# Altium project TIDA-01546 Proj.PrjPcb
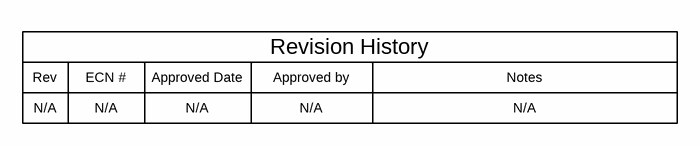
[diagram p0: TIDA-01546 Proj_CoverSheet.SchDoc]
CopyrightYear: 2017; PCB_Layout: Who did the Layout?; PCB_Rev: E2; PRJ_Customer: Public Release; PRJ_Engineer: Enter name of project lead; PRJ_Number: TIDA-01546; PRJ_Title: Change in menu Project|Project Options|Parameters; SCH_Rev: E2; TechSupport: http://www.ti.com/support; TID: TIDA-01546
5 sheets, 178 parts. Net scope: flat (ports and power ports of the same name join across sheets).
Board file: TIDA-01546 Proj_PCB.PcbDoc
Sheets:
  TIDA-01546 Proj_CoverSheet.SchDoc
  TIDA-01546 Proj_SysMonitoring.SchDoc
  TIDA-01546 Proj_BatMonitoring.SchDoc
  TIDA-01546 Proj_SysLoad.SchDoc
  TIDA-01546 Proj_EVM_Hardware.SchDoc

## Sheet TIDA-01546 Proj_CoverSheet.SchDoc
size 431 x 279 mm; Date: Not shown in title block; ApprovedBy: Not shown in title block; CheckedBy: Not shown in title block; Author: Not shown in title block; CompanyName: Not shown in title block; Organization: Not shown in title block; Address1: Not shown in title block; Address2: Not shown in title block; Address3: Not shown in title block; Address4: Not shown in title block; DocumentNumber: 1; Revision: Use project parameter SCH_Rev; SheetNumber: 1; SheetTotal: 3; PageSetup: Record=PageOptions¦CenterHorizontal=True¦CenterVertical=True¦PrintScale=0.64¦XCorrection=1.00¦YCorrection=1.00¦PrintKind=0¦BorderSize=5000000¦LeftOffset=0¦BottomOffset=0¦Orientation=2¦PaperLength=1000¦PaperWidth=1000¦Scale=100¦PaperSource=15¦PrintQuality=600¦MediaType=1¦DitherType=10¦PrintScaleMode=1¦PaperKind=Letter

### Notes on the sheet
- Rev
- N/A
- ECN #
- Approved Date
- Approved by
- Revision History
- Notes

## Sheet TIDA-01546 Proj_SysMonitoring.SchDoc
size 431 x 279 mm; Date: Not shown in title block; ApprovedBy: Not shown in title block; CheckedBy: Not shown in title block; Author: Not shown in title block; CompanyName: Not shown in title block; Engineer: Not shown in title block; Organization: Not shown in title block; Address1: Not shown in title block; Address2: Not shown in title block; Address3: Not shown in title block; Address4: Not shown in title block; DocumentNumber: 1; Revision: Use project parameter SCH_Rev; SheetNumber: 2; SheetTotal: 3; PageSetup: Record=PageOptions¦CenterHorizontal=True¦CenterVertical=True¦PrintScale=1.00¦XCorrection=1.00¦YCorrection=1.00¦PrintKind=0¦BorderSize=5000000¦LeftOffset=0¦BottomOffset=0¦Orientation=2¦PaperLength=1000¦PaperWidth=1000¦Scale=100¦PaperSource=15¦PrintQuality=600¦MediaType=1¦DitherType=10¦PaperKind=Letter¦PrintScaleMode=1
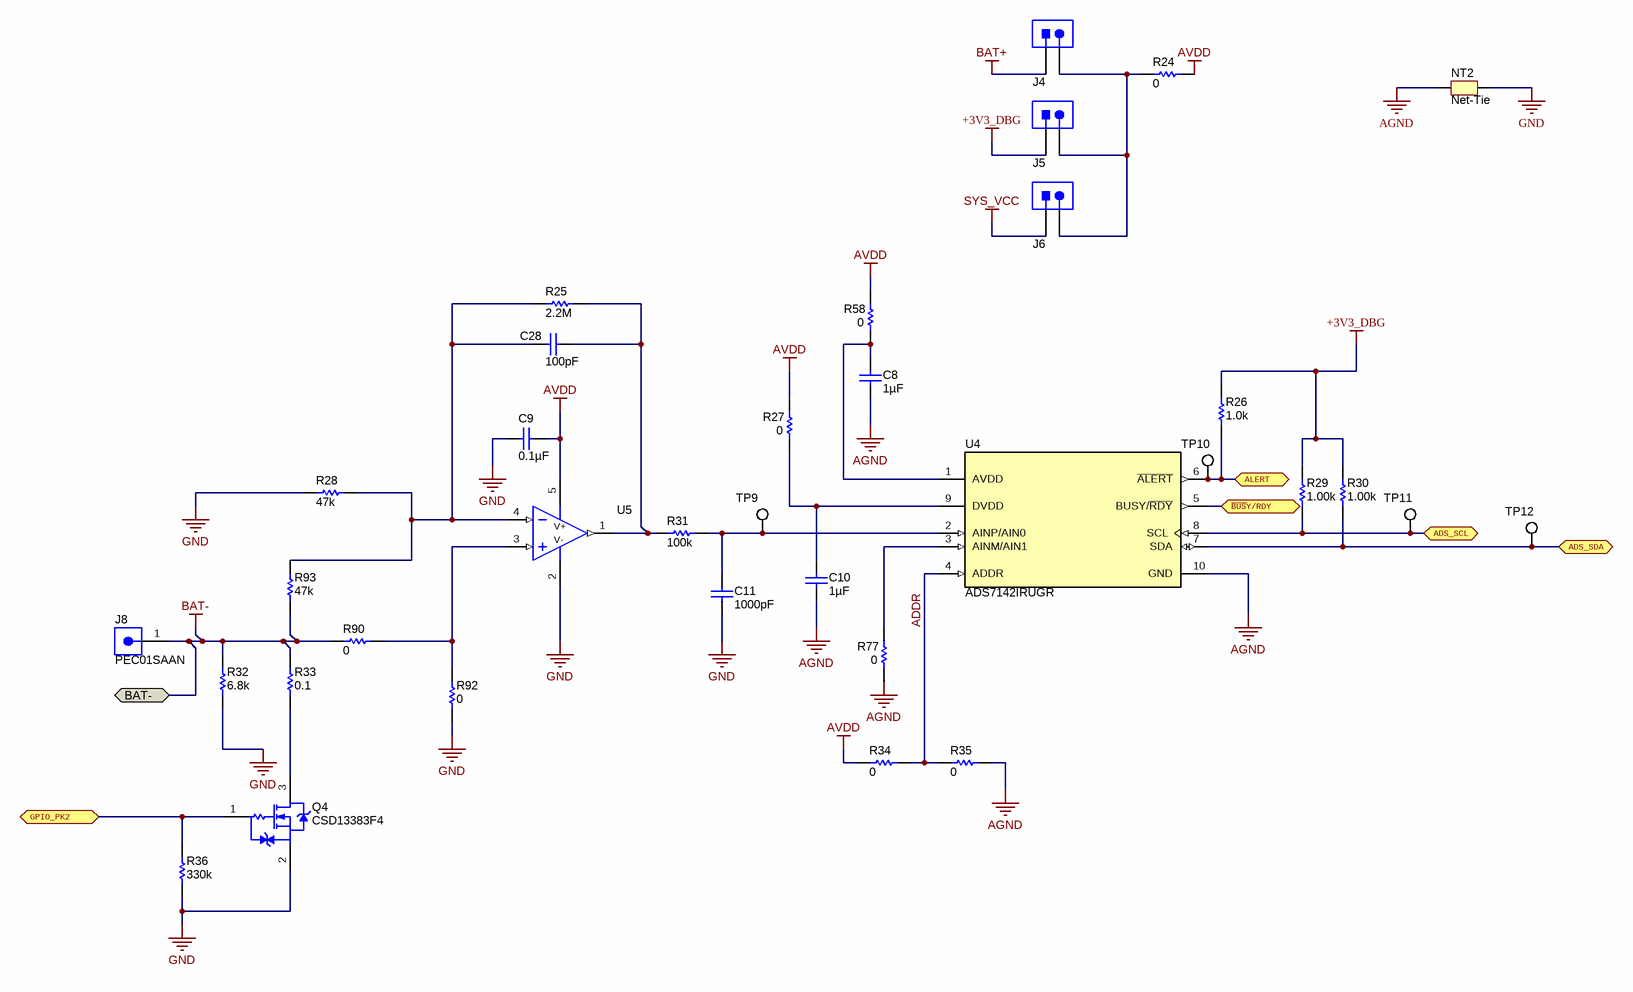
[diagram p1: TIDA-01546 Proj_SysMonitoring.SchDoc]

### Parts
C8  ValueDisplayed: 1µF  [0805_HV]  (hidden comment: GRM21BR71H105KA12L)
C9  ValueDisplayed: 0.1µF  [0402_065]  (hidden comment: 160R07X104KV4T)
C10  ValueDisplayed: 1µF  [0805_HV]  (hidden comment: GRM21BR71H105KA12L)
C11  ValueDisplayed: 1000pF  [1206_190]  (hidden comment: 202R18W102KV4E)
C28  ValueDisplayed: 100pF  [0402]  (hidden comment: 0402YC101KAT2A)
J4  PEC02SAAN  [CONN_PEC02SAAN]  (value not drawn)
J5  PEC02SAAN  [CONN_PEC02SAAN]  (value not drawn)
J6  PEC02SAAN  [CONN_PEC02SAAN]  (value not drawn)
J8  PEC01SAAN  [Sullins_PEC01SAAN]
NT2  Net-Tie  [Net-Tie_50milWide_30milLong]  (net tie, no BOM)
Q4  CSD13383F4  [YJC0003A]
R24  ValueDisplayed: 0  [0402]  (hidden comment: RC0402JR-070RL)
R25  ValueDisplayed: 2.2M  [0603]  (hidden comment: CRCW06032M20JNEA)
R26  value 1.0k  [0603]  (hidden comment: CRCW06031K00JNEA)
R27  ValueDisplayed: 0  [0402]  (hidden comment: RC0402JR-070RL)
R28  ValueDisplayed: 47k  [0603]  (hidden comment: CRCW060347K0JNEA)
R29  ValueDisplayed: 1.00k  [0603]  (hidden comment: CRCW06031K00FKEA)
R30  ValueDisplayed: 1.00k  [0603]  (hidden comment: CRCW06031K00FKEA)
R31  ValueDisplayed: 100k  [0603]  (hidden comment: CRCW0603100KJNEA)
R32  ValueDisplayed: 6.8k  [2010]  (hidden comment: CRCW20106K80JNEF)
R33  ValueDisplayed: 0.1  [2010]  (hidden comment: WSL2010R1000FEA)
R34  ValueDisplayed: 0  [0402]  (hidden comment: RC0402JR-070RL)
R35  ValueDisplayed: 0  [0402]  (hidden comment: RC0402JR-070RL)
R36  ValueDisplayed: 330k  [0805_HV]  (hidden comment: CRCW0805330KJNEA)
R58  ValueDisplayed: 0  [0402]  (hidden comment: RC0402JR-070RL)
R77  ValueDisplayed: 0  [0402]  (hidden comment: RC0402JR-070RL)
R90  ValueDisplayed: 0  [0402]  (hidden comment: RC0402JR-070RL)
R92  ValueDisplayed: 0  [0402]  (hidden comment: RC0402JR-070RL)
R93  ValueDisplayed: 47k  [0402]  (hidden comment: CRCW040247K0JNED)
TP9  5002  [Keystone5002]  (value not drawn)
TP10  5002  [Keystone5002]  (value not drawn)
TP11  5002  [Keystone5002]  (value not drawn)
TP12  5002  [Keystone5002]  (value not drawn)
U4  PartNumber: ADS7142IRUGR  [RUG0010A]  (hidden comment: CMP-0065258-3)
U5  LPV521MG  [DCK0005A_N]  (value not drawn)

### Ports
ADS_SCL, ADS_SDA, ALERT, BAT- (bidir), GPIO_PK2, ~{BUS}Y/RDY

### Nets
+3V3_DBG: J5.1 R26.1 R29.1 R30.1
AGND: C8.1 C10.1 NT2.1 R35.2 R77.1 U4.10(GND)
AVDD: C9.1 R24.2 R27.2 R34.1 R58.2 U5.5(V+)
BAT+: J4.1
BAT-: J8.1 R32.1 R33.1 R90.1 R93.1 ; port BAT-
GND: C9.2 C11.1 NT2.2 Q4.2(S) R28.1 R32.2 R36.2 R92.1 U5.2(V-)
SYS_VCC: J6.1
ADDR: R34.2 R35.1 U4.4(ADDR)
ADS_SCL: R29.2 TP11.1 U4.8(SCL) ; port ADS_SCL
ADS_SDA: R30.2 TP12.1 U4.7(SDA) ; port ADS_SDA
ALERT: R26.2 TP10.1 U4.6(~{ALERT}) ; port ALERT
~{BUS}Y/RDY: U4.5(BUSY/~{RDY}) ; port ~{BUS}Y/RDY
GPIO_PK2: Q4.1(G) R36.1 ; port GPIO_PK2
NetC8_2: C8.2 R58.1 U4.1(AVDD)
NetC10_2: C10.2 R27.1 U4.9(DVDD)
NetC11_2: C11.2 R31.2 TP9.1 U4.2(AINP/AIN0)
NetC28_1: C28.1 R25.2 R31.1 U5.1(OUT)
NetC28_2: C28.2 R25.1 R28.2 R93.2 U5.4(IN-)
NetJ4_2: J4.2 J5.2 J6.2 R24.1
NetQ4_3: Q4.3(D) R33.2
NetR77_2: R77.2 U4.3(AINM/AIN1)
NetR90_2: R90.2 R92.2 U5.3(IN+)

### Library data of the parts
C8 C10 = GRM21BR71H105KA12L: CAP, CERM, 1 µF, 50 V, +/- 10%, X7R, 0805; Manufacturer: MuRata; Polarized: N; CompType: Capacitor; Value: 1uF; U/M: EA; Cap_F: 0.000001; Tolerance_%: 10; Value1: Unknown; VDC_V: 50; Value2: 50V; TaMin_C: -55; TaMax_C: 125; Cap_Case: 0805; AEC Category: Q200
C9 = 160R07X104KV4T: CAP, CERM, 0.1 µF, 16 V,+/- 10%, X5R, 0402; Manufacturer: Johanson Technology; Polarized: N; CompType: Capacitor; Value: 0.1uF; U/M: EA; Cap_F: 0.0000001; Tolerance_%: 10; VDC_V: 16; Value2: 16V; TaMin_C: -55; TaMax_C: 85; Cap_Case: 0402; SizeArea_mm2: 0.5; SizeAreaWB_mm2: 3; SizeX_mm: 1; SizeZ_mm: 0.65; AEC Category: Q200; Green_Lifecycle: Not Set; Green_REACh: Incomplete
C11 = 202R18W102KV4E: CAP, CERM, 1000 pF, 2000 V,+/- 10%, X7R, 1206; Manufacturer: Johanson Technology; Polarized: N; CompType: Capacitor; Value: 1000pF; U/M: EA; Cap_F: 0.000000001; Tolerance_%: 10; VDC_V: 2000; Value2: 2000V; TaMin_C: -55; TaMax_C: 125; Cap_Case: 1206; SizeArea_mm2: 5.12; SizeAreaWB_mm2: 10.92; SizeX_mm: 3.2; SizeY_mm: 1.6; SizeZ_mm: 1.9; AEC Category: Q200
C28 = 0402YC101KAT2A: CAP, CERM, 100 pF, 16 V,+/- 10%, X7R, 0402; Manufacturer: AVX; Polarized: N; CompType: Capacitor; Value: 100pF; U/M: EA; Cap_F: 0.0000000001; Tolerance_%: 10; VDC_V: 16; Value2: 16V; TaMin_C: -55; TaMax_C: 125; SizeArea_mm2: 0.5; SizeAreaWB_mm2: 3; SizeX_mm: 1; SizeZ_mm: 0.6; AEC Category: Q200
J4-J6 = PEC02SAAN: Header, 100mil, 2x1, Tin, TH; Manufacturer: Sullins Connector Solutions; SymbolCreator: a0412235; Pitch_mm: 2.54; Gender: Male; Shrouded: N; Row_Count: 1; Current_A: 3; Voltage_V: 1800; Cert_UL: Y
J8 = PEC01SAAN: Header, 1x1, Tin, TH; Manufacturer: Sullins Connector Solutions; SymbolCreator: a0412235; Pitch_mm: 2.54; Gender: Male; Shrouded: N; Row_Count: 1; Current_A: 3; Voltage_V: 1800; Cert_UL: Y; Green_Lifecycle: Not Set; Green_REACh: Incomplete
NT2 = Net-Tie: Single point connection between nets.; SymbolCreator: codlsc
Q4 = CSD13383F4: MOSFET, N-CH, 12 V, 2.9 A, YJC0003A (PICOSTAR-3); Manufacturer: Texas Instruments; Alternate Manufacturer: None; SymbolCreator: a0411947; U/M: EA; ChType: N; Value: 12V; VdsMax_V: 12; Value1: 0.044 ohm; Rdson45_ohm: 0.044; Value2: 2 nC; QgTyp_nC: 2; Vgs_V: 10; IdsMax_A: 2.9; SizeAreaWB_mm2: 3.327225; SizeArea_mm2: 0.657225; SizeX_mm: 1.035; SizeY_mm: 0.635; SizeZ_mm: 0.35; AEC Category: Q101
R24 R27 R34 R35 R58 R77 R90 R92 = RC0402JR-070RL: RES, 0, 5%, 0.063 W, 0402; Manufacturer: Yageo America; CompType: Resistor; Value: 0; Value_Code: 0000; Tolerance_%: 5; Power_W: 0.063; Value2: 0.063W; VDC_V: 50; TempCo: 200 ppm/C; EIA_Code: E24; U/M: EA; AEC Category: Q200
R25 = CRCW06032M20JNEA: RES, 2.2 M, 5%, 0.1 W, 0603; Manufacturer: Vishay-Dale; CompType: Resistor; Value: 2.2Meg; Res_ohm: 2200000; Value_Code: 2M20; Tolerance_%: 5; Power_W: 0.1; Value2: 0.1W; VDC_V: 75; TempCo: 200 ppm/C; SizeArea_mm2: 1.28; SizeX_mm: 1.6; SizeY_mm: 0.8; SizeZ_mm: 1; EIA_Code: E24; U/M: EA; AEC Category: Q200
R26 = CRCW06031K00JNEA: RES, 1.0k ohm, 5%, 0.1W, 0603; Manufacturer: Vishay-Dale; CompType: Resistor; Res_ohm: 1000; Value_Code: 1k00; Tolerance_%: 5; Power_W: 0.1; VDC_V: 75; TempCo: 200 ppm/C; EIA_Code: E24; U/M: EA
R28 = CRCW060347K0JNEA: RES, 47 k, 5%, 0.1 W, 0603; Manufacturer: Vishay-Dale; CompType: Resistor; Value: 47k; Res_ohm: 47000; Value_Code: 47k0; Tolerance_%: 5; Power_W: 0.1; Value2: 0.1W; VDC_V: 75; TempCo: 200 ppm/C; SizeArea_mm2: 1.28; SizeX_mm: 1.6; SizeY_mm: 0.8; SizeZ_mm: 1; EIA_Code: E24; U/M: EA; AEC Category: Q200; Green_Lifecycle: Active; Green_REACh: Passed
R29 R30 = CRCW06031K00FKEA: RES, 1.00 k, 1%, 0.1 W, 0603; Manufacturer: Vishay-Dale; CompType: Resistor; Value: 1.00k; Res_ohm: 1000; Value_Code: 1k00; Tolerance_%: 1; Power_W: 0.1; Value2: 0.1W; VDC_V: 75; TempCo: 100 ppm/C; EIA_Code: E96; U/M: EA; AEC Category: Q200; SizeArea_mm2: 1.28; SizeX_mm: 1.6; SizeY_mm: 0.8; Green_Lifecycle: Active; Green_REACh: Passed
R31 = CRCW0603100KJNEA: RES, 100 k, 5%, 0.1 W, 0603; Manufacturer: Vishay-Dale; CompType: Resistor; Value: 100k; Res_ohm: 100000; Tolerance_%: 5; Power_W: 0.1; Value2: 0.1W; VDC_V: 75; TempCo: 200 ppm/C; SizeArea_mm2: 1.28; SizeX_mm: 1.6; SizeY_mm: 0.8; SizeZ_mm: 1; EIA_Code: E24; U/M: EA; AEC Category: Q200; Green_Lifecycle: Active; Green_REACh: Passed
R32 = CRCW20106K80JNEF: RES, 6.8 k, 5%, 0.75 W, AEC-Q200 Grade 0, 2010; Manufacturer: Vishay-Dale; CompType: Resistor; Value: 6.8k; Res_ohm: 6800; Value_Code: 6k80; Tolerance_%: 5; Power_W: 0.75; Value2: 0.75W; VDC_V: 400; TempCo: 200 ppm/C; SizeArea_mm2: 12.5; SizeY_mm: 2.5; SizeZ_mm: 1.66; EIA_Code: E24; U/M: EA; AEC Category: Q200; AEC Qualified: Y; AEC Grade: 0
R33 = WSL2010R1000FEA: RES, 0.1, 1%, 0.5 W, 2010; Manufacturer: Vishay-Dale; CompType: Resistor; Value: 0.1; Value_Code: R100; Tolerance_%: 1; Power_W: 0.5; Value2: 0.5W; TempCo: 75 ppm/C; SizeArea_mm2: 12.5; SizeX_mm: 5; SizeY_mm: 2.5; SizeZ_mm: 1.66; EIA_Code: E96; U/M: EA; AEC Category: Q200
R36 = CRCW0805330KJNEA: RES, 330 k, 5%, 0.125 W, 0805; Manufacturer: Vishay-Dale; CompType: Resistor; Value: 330k; Res_ohm: 330000; Tolerance_%: 5; Power_W: 0.125; Value2: 0.125W; VDC_V: 150; TempCo: 200 ppm/C; SizeArea_mm2: 2.5; SizeX_mm: 2; SizeY_mm: 1.25; SizeZ_mm: 1.45; EIA_Code: E24; U/M: EA; AEC Category: Q200
R93 = CRCW040247K0JNED: RES, 47 k, 5%, 0.063 W, 0402; Manufacturer: Vishay-Dale; CompType: Resistor; Value: 47k; Res_ohm: 47000; Value_Code: 47k0; Tolerance_%: 5; Power_W: 0.063; Value2: 0.063W; VDC_V: 50; TempCo: 200 ppm/C; SizeArea_mm2: 0.5; SizeX_mm: 1; SizeZ_mm: 0.6; EIA_Code: E24; U/M: EA; AEC Category: Q200; Green_Lifecycle: Active; Green_REACh: Passed
TP9-TP12 = 5002: Test Point, Miniature, White, TH; Manufacturer: Keystone; CompType: Test Point Loop; U/M: EA
U4 = CMP-0065258-3: Nanopower, Ultra-Small Size, Sensor Monitor with I2C Interface and Alert Output, RUG0010A (X2QFN-10); Alternate PartNumber: ADS7142IRUGT; Manufacturer: Texas Instruments; SizeArea_mm2: 3.0; SizeAreaWB_mm2: 7.5; SizeX_mm: 1.5; SizeY_mm: 2.0; SizeZ_mm: 0.4; CompType: IC; U/M: EA
U5 = LPV521MG: Nanopower 400nA, 1.8V, R-R I/O CMOS Op Amp, DCK0005A; Manufacturer: Texas Instruments; CompType: OpAmp IC

## Sheet TIDA-01546 Proj_BatMonitoring.SchDoc
size 431 x 279 mm; Date: Not shown in title block; ApprovedBy: Not shown in title block; CheckedBy: Not shown in title block; Author: Not shown in title block; CompanyName: Not shown in title block; Engineer: Not shown in title block; Organization: Not shown in title block; Address1: Not shown in title block; Address2: Not shown in title block; Address3: Not shown in title block; Address4: Not shown in title block; DocumentNumber: 1; Revision: Use project parameter SCH_Rev; SheetNumber: 2; SheetTotal: 3; PageSetup: Record=PageOptions¦CenterHorizontal=True¦CenterVertical=True¦PrintScale=1.00¦XCorrection=1.00¦YCorrection=1.00¦PrintKind=0¦BorderSize=5000000¦LeftOffset=0¦BottomOffset=0¦Orientation=2¦PaperLength=1000¦PaperWidth=1000¦Scale=100¦PaperSource=15¦PrintQuality=600¦MediaType=1¦DitherType=10¦PaperKind=Letter¦PrintScaleMode=1
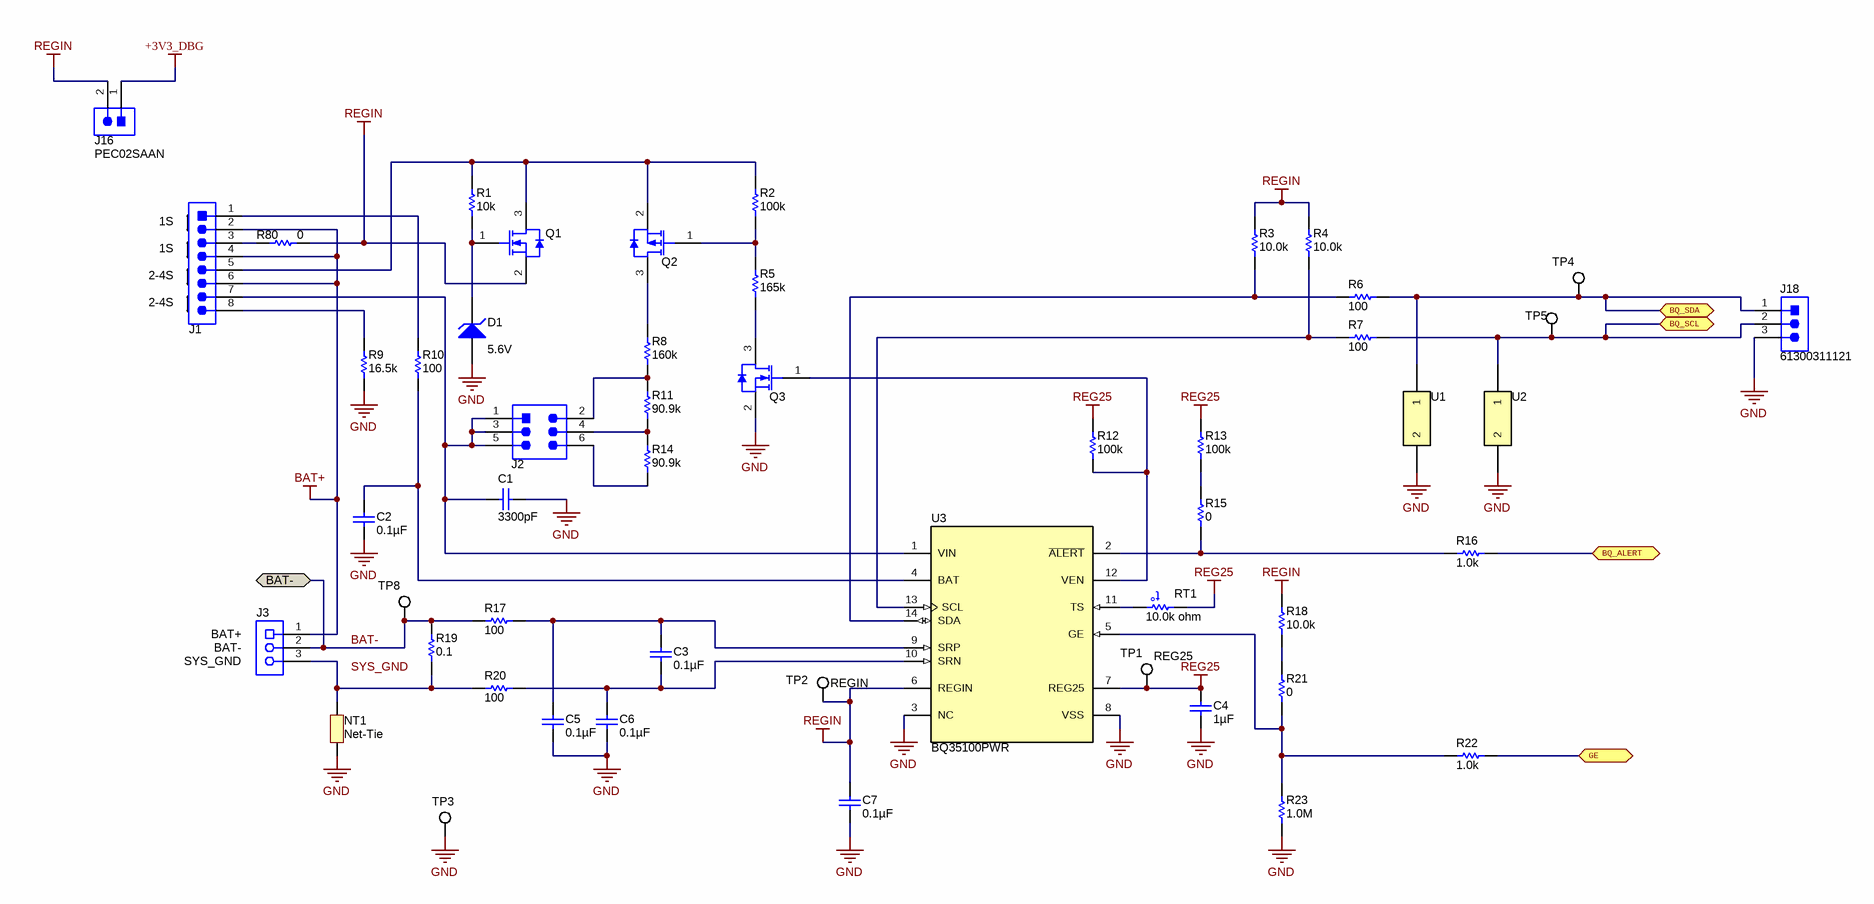
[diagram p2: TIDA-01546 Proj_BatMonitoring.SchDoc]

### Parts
C1  ValueDisplayed: 3300pF  [0603]  (hidden comment: GRM188R71H332KA01D)
C2  ValueDisplayed: 0.1µF  [0603]  (hidden comment: GRM188R71H104KA93D)
C3  ValueDisplayed: 0.1µF  [0603]  (hidden comment: GRM188R71H104KA93D)
C4  ValueDisplayed: 1µF  [0805_HV]  (hidden comment: GRM21BR71H105KA12L)
C5  ValueDisplayed: 0.1µF  [0603]  (hidden comment: GRM188R71H104KA93D)
C6  ValueDisplayed: 0.1µF  [0603]  (hidden comment: GRM188R71H104KA93D)
C7  ValueDisplayed: 0.1µF  [0603]  (hidden comment: GRM188R71H104KA93D)
D1  value 5.6V  [SOD-523]  (hidden comment: BZT52C5V6T-7)
J1  PEC08SAAN  [SULLINS_PEC08SAAN]  (value not drawn)
J2  PEC03DAAN  [SULLINS_PEC03DAAN]  (value not drawn)
J3  39357-0003  [Molex_39357-0003]  (value not drawn)
J16  PEC02SAAN  [CONN_PEC02SAAN]
J18  61300311121  [WURTH_61300311121]
NT1  Net-Tie  [Net-Tie_10mil]  (net tie, no BOM)
Q1  2N7002-7-F  [SOT-23]  (value not drawn)
Q2  BSS84W-7-F  [SOT-323]  (value not drawn)
Q3  BSS138W-7-F  [SOT-323]  (value not drawn)
R1  value 10k  [0603]  (hidden comment: CRCW060310K0JNEA)
R2  ValueDisplayed: 100k  [0603]  (hidden comment: CRCW0603100KFKEA)
R3  ValueDisplayed: 10.0k  [0603]  (hidden comment: CRCW060310K0FKEA)
R4  ValueDisplayed: 10.0k  [0603]  (hidden comment: CRCW060310K0FKEA)
R5  ValueDisplayed: 165k  [0603]  (hidden comment: CRCW0603165KFKEA)
R6  ValueDisplayed: 100  [0603]  (hidden comment: CRCW0603100RFKEA)
R7  ValueDisplayed: 100  [0603]  (hidden comment: CRCW0603100RFKEA)
R8  ValueDisplayed: 160k  [0603]  (hidden comment: RG1608P-164-B-T5)
R9  ValueDisplayed: 16.5k  [0603]  (hidden comment: RG1608P-1652-B-T5)
R10  ValueDisplayed: 100  [0603]  (hidden comment: CRCW0603100RFKEA)
R11  ValueDisplayed: 90.9k  [0603]  (hidden comment: RG1608P-9092-B-T5)
R12  ValueDisplayed: 100k  [0603]  (hidden comment: CRCW0603100KFKEA)
R13  ValueDisplayed: 100k  [0603]  (hidden comment: CRCW0603100KFKEA)
R14  ValueDisplayed: 90.9k  [0603]  (hidden comment: RG1608P-9092-B-T5)
R15  ValueDisplayed: 0  [0402]  (hidden comment: RC0402JR-070RL)
R16  value 1.0k  [0603]  (hidden comment: CRCW06031K00JNEA)
R17  ValueDisplayed: 100  [0603]  (hidden comment: CRCW0603100RFKEA)
R18  ValueDisplayed: 10.0k  [0603]  (hidden comment: CRCW060310K0FKEA)
R19  ValueDisplayed: 0.1  [2010]  (hidden comment: WSL2010R1000FEA)
R20  ValueDisplayed: 100  [0603]  (hidden comment: CRCW0603100RFKEA)
R21  ValueDisplayed: 0  [0402]  (hidden comment: RC0402JR-070RL)
R22  value 1.0k  [0603]  (hidden comment: CRCW06031K00JNEA)
R23  ValueDisplayed: 1.0M  [0603]  (hidden comment: CRCW06031M00JNEA)
R80  ValueDisplayed: 0  [0402]  (hidden comment: RC0402JR-070RL)
RT1  value 10.0k ohm  [Thermistor_103AT-2]  (hidden comment: 103AT-2)
TP1  5002  [Keystone5002]  (value not drawn)
TP2  5002  [Keystone5002]  (value not drawn)
TP3  5002  [Keystone5002]  (value not drawn)
TP4  5002  [Keystone5002]  (value not drawn)
TP5  5002  [Keystone5002]  (value not drawn)
TP8  5002  [Keystone5002]  (value not drawn)
U1  TPD1E10B06DPYR  [DPY0002A]  (value not drawn)
U2  TPD1E10B06DPYR  [DPY0002A]  (value not drawn)
U3  BQ35100PWR  [PW0014A_N]

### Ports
BAT- (bidir), BQ_ALERT, BQ_SCL, BQ_SDA, GE

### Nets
+3V3_DBG: J16.1
BAT+: J1.2 J1.4 J1.6 J3.1
BAT-: J3.2 R17.1 R19.1 TP8.1 ; port BAT-
GND: C1.2 C2.1 C4.1 C5.1 C6.1 C7.1 D1.2(A) J18.3 NT1.2 Q3.2(S) R9.2 R23.2 TP3.1 U1.2 U2.2 U3.3(NC) U3.8(VSS)
REG25: C4.2 R12.1 R13.1 RT1.1 TP1.1 U3.7(REG25)
REGIN: C7.2 J16.2 Q1.2(S) R3.1 R4.1 R18.1 R80.1 TP2.1 U3.6(REGIN)
BQ_ALERT: R16.2 ; port BQ_ALERT
BQ_SCL: J18.2 R7.2 TP5.1 U2.1 ; port BQ_SCL
BQ_SDA: J18.1 R6.2 TP4.1 U1.1 ; port BQ_SDA
GE: R22.2 ; port GE
NetC1_1: C1.1 J1.7 J2.1 J2.3 J2.5 U3.1(VIN)
NetC2_2: C2.2 R10.2 U3.4(BAT)
NetC3_1: C3.1 C6.2 R20.2 U3.10(SRN)
NetC3_2: C3.2 C5.2 R17.2 U3.9(SRP)
NetD1_1: D1.1(K) Q1.1(G) R1.2
NetJ1_1: J1.1 R10.1
NetJ1_3: J1.3 R80.2
NetJ1_5: J1.5 Q1.3(D) Q2.2(S) R1.1 R2.1
NetJ1_8: J1.8 R9.1
NetJ2_2: J2.2 R8.2 R11.1
NetJ2_4: J2.4 R11.2 R14.2
NetJ2_6: J2.6 R14.1
NetJ3_3: J3.3 NT1.1 R19.2 R20.1
NetQ2_1: Q2.1(G) R2.2 R5.1
NetQ2_3: Q2.3(D) R8.1
NetQ3_1: Q3.1(G) R12.2 U3.12(VEN)
NetQ3_3: Q3.3(D) R5.2
NetR3_2: R3.2 R6.1 U3.14(SDA)
NetR4_2: R4.2 R7.1 U3.13(SCL)
NetR13_2: R13.2 R15.1
NetR15_2: R15.2 R16.1 U3.2(~{ALERT})
NetR18_2: R18.2 R21.1
NetR21_2: R21.2 R22.1 R23.1 U3.5(GE)
NetRT1_2: RT1.2 U3.11(TS)

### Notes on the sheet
- (near J1) 1S
- (near J1) 2-4S
- (near J3) BAT+
- (near J3) BAT-
- (near J3) SYS_GND
- (near TP2) REGIN
- (near TP1) REG25
- Labels drawn without touching a wire or pin: SYS_GND

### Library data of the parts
C1 = GRM188R71H332KA01D: CAP, CERM, 3300 pF, 50 V, +/- 10%, X7R, 0603; Manufacturer: MuRata; Polarized: N; CompType: Capacitor; Value: 3300pF; U/M: EA; Cap_F: 0.0000000033; Tolerance_%: 10; Value1: Unknown; VDC_V: 50; Value2: 50V; TaMin_C: -55; TaMax_C: 125; AEC Category: Q200
C2 C3 C5-C7 = GRM188R71H104KA93D: CAP, CERM, 0.1 µF, 50 V, +/- 10%, X7R, 0603; Manufacturer: MuRata; Polarized: N; CompType: Capacitor; Value: 0.1uF; U/M: EA; Cap_F: 0.0000001; Tolerance_%: 10; Value1: Unknown; VDC_V: 50; Value2: 50V; TaMin_C: -55; TaMax_C: 125; AEC Category: Q200
C4 = GRM21BR71H105KA12L: as C8 on sheet TIDA-01546 Proj_SysMonitoring
D1 = BZT52C5V6T-7: Diode, Zener, 5.6 V, 300 mW, SOD-523; Manufacturer: Diodes Inc.; SymbolCreator: a0412235; U/M: EA; Power_W: 0.3; Vz_V: 5.6; Value1: 0.3W; RJA_CperW: 417; AEC Category: Q101
J1 = PEC08SAAN: Header, 100mil, 8x1, Tin, TH; Manufacturer: Sullins Connector Solutions; SymbolCreator: a0411947; Pitch_mm: 2.54; Gender: Male; Shrouded: N; Row_Count: 1; Current_A: 3; Voltage_V: 1800; Cert_UL: Y
J2 = PEC03DAAN: Header, 100mil, 3x2, Tin, TH; Manufacturer: Sullins Connector Solutions; SymbolCreator: a0412235; Pitch_mm: 2.54; Gender: Male; Shrouded: N; Row_Count: 2; Current_A: 3; Voltage_V: 1800; Cert_UL: Y
J3 = 39357-0003: Terminal Block, 3.5 mm, 3x1, Tin, TH; Manufacturer: Molex; SymbolCreator: a0412235
J16 = PEC02SAAN: Header, 100mil, 2x1, Tin, TH; Manufacturer: Sullins Connector Solutions; SymbolCreator: a0412235; Pitch_mm: 2.54; Gender: Male; Shrouded: N; Row_Count: 1; Current_A: 3; Voltage_V: 1800; Cert_UL: Y; Green_Lifecycle: Not Set; Green_REACh: Incomplete
J18 = 61300311121: Header, 2.54 mm, 3x1, Gold, TH; Manufacturer: Wurth Elektronik; SymbolCreator: a0799628; Green_Lifecycle: Active; Green_REACh: Passed
NT1 = Net-Tie: as NT2 on sheet TIDA-01546 Proj_SysMonitoring
Q1 = 2N7002-7-F: MOSFET, N-CH, 60 V, 0.17 A, SOT-23; Manufacturer: Diodes Inc.; Alternate Manufacturer: None; U/M: EA; ChType: N; Value: 60V; VdsMax_V: 60; Value1: 7.5 ohm; Rdson45_ohm: 7.5; Value2: 223 nC; QgTyp_nC: 223; Vgs_V: 20; IdsMax_A: 0.17; AEC Category: Q101
Q2 = BSS84W-7-F: MOSFET, P-CH, -50 V, -0.13 A, SOT-323; Manufacturer: Diodes Inc.; Alternate Manufacturer: None; U/M: EA; ChType: P; Value: -50V; Value1: 10 ohm; Rdson45_ohm: 10; Value2: ? nC; Vgs_V: -20; AEC Category: Q101
Q3 = BSS138W-7-F: MOSFET, N-CH, 50 V, 0.2 A, SOT-323; Manufacturer: Diodes Inc.; Alternate Manufacturer: None; U/M: EA; ChType: N; Value: 50V; VdsMax_V: 50; Value1: 3.5 ohm; Rdson45_ohm: 3.5; Value2: ? nC; Vgs_V: 1.5; IdsMax_A: 0.2; AEC Category: Q101
R1 = CRCW060310K0JNEA: RES, 10k ohm, 5%, 0.1W, 0603; Manufacturer: Vishay-Dale; CompType: Resistor; Res_ohm: 10000; Value_Code: 10k0; Tolerance_%: 5; Power_W: 0.1; VDC_V: 75; TempCo: 200 ppm/C; EIA_Code: E24; U/M: EA
R2 R12 R13 = CRCW0603100KFKEA: RES, 100 k, 1%, 0.1 W, 0603; Manufacturer: Vishay-Dale; CompType: Resistor; Value: 100k; Res_ohm: 100000; Tolerance_%: 1; Power_W: 0.1; Value2: 0.1W; VDC_V: 75; TempCo: 100 ppm/C; EIA_Code: E96; U/M: EA; AEC Category: Q200
R3 R4 R18 = CRCW060310K0FKEA: RES, 10.0 k, 1%, 0.1 W, 0603; Manufacturer: Vishay-Dale; CompType: Resistor; Value: 10.0k; Res_ohm: 10000; Value_Code: 10k0; Tolerance_%: 1; Power_W: 0.1; Value2: 0.1W; VDC_V: 75; TempCo: 100 ppm/C; EIA_Code: E96; U/M: EA; AEC Category: Q200
R5 = CRCW0603165KFKEA: RES, 165 k, 1%, 0.1 W, 0603; Manufacturer: Vishay-Dale; CompType: Resistor; Value: 165k; Res_ohm: 165000; Tolerance_%: 1; Power_W: 0.1; Value2: 0.1W; VDC_V: 75; TempCo: 100 ppm/C; EIA_Code: E96; U/M: EA; AEC Category: Q200
R6 R7 R10 R17 R20 = CRCW0603100RFKEA: RES, 100, 1%, 0.1 W, 0603; Manufacturer: Vishay-Dale; CompType: Resistor; Value: 100; Value_Code: 100R; Tolerance_%: 1; Power_W: 0.1; Value2: 0.1W; VDC_V: 75; TempCo: 100 ppm/C; EIA_Code: E96; U/M: EA; AEC Category: Q200
R8 = RG1608P-164-B-T5: RES, 160 k, 0.1%, 0.1 W, 0603; Manufacturer: Susumu Co Ltd; CompType: Resistor; Value: 160k; Res_ohm: 160000; Tolerance_%: 0.1; Value2: 0.1W; VDC_V: 75; TempCo: 25 ppm/C; EIA_Code: E192; U/M: EA; AEC Category: Q200
R9 = RG1608P-1652-B-T5: RES, 16.5 k, 0.1%, 0.1 W, 0603; Manufacturer: Susumu Co Ltd; CompType: Resistor; Value: 16.5k; Res_ohm: 16500; Value_Code: 16k5; Tolerance_%: 0.1; Value2: 0.1W; VDC_V: 75; TempCo: 25 ppm/C; EIA_Code: E192; U/M: EA; AEC Category: Q200
R11 R14 = RG1608P-9092-B-T5: RES, 90.9 k, 0.1%, 0.1 W, 0603; Manufacturer: Susumu Co Ltd; CompType: Resistor; Value: 90.9k; Res_ohm: 90900; Value_Code: 90k9; Tolerance_%: 0.1; Value2: 0.1W; VDC_V: 75; TempCo: 25 ppm/C; EIA_Code: E192; U/M: EA; AEC Category: Q200
R15 R21 R80 = RC0402JR-070RL: as R24 on sheet TIDA-01546 Proj_SysMonitoring
R16 R22 = CRCW06031K00JNEA: as R26 on sheet TIDA-01546 Proj_SysMonitoring
R19 = WSL2010R1000FEA: as R33 on sheet TIDA-01546 Proj_SysMonitoring
R23 = CRCW06031M00JNEA: RES, 1.0 M, 5%, 0.1 W, 0603; Manufacturer: Vishay-Dale; CompType: Resistor; Value: 1.0Meg; Res_ohm: 1000000; Value_Code: 1M00; Tolerance_%: 5; Power_W: 0.1; Value2: 0.1W; VDC_V: 75; TempCo: 200 ppm/C; EIA_Code: E24; U/M: EA; AEC Category: Q200
RT1 = 103AT-2: Thermistor NTC, 10.0k ohm, 1%, Disc, 5x8.4 mm; Manufacturer: SEMITEC Corporation; Tolerance_%: 1; Power_W: 0.01; TaMin_C: -50; TaMax_C: 110; U/M: EA
TP1-TP5 TP8 = 5002: as TP9 on sheet TIDA-01546 Proj_SysMonitoring
U1 U2 = TPD1E10B06DPYR: ESD in 0402 Package with 10 pF Capacitance and 6 V Breakdown, 1 Channel, -40 to +125 degC, 2-pin X2SON (DPY), Green (RoHS & no Sb/Br); Manufacturer: Texas Instruments; Alternate PartNumber: Equivalent; Breakdown Voltage(Min)(V): 6; Eco-Plan: TBD; IEC 61000-4-2 Air-Gap(+/- kV): 30; IO Capacitance(Typ)(pF): 10; SubFamily: ESD Solution
U3 = BQ35100PWR: Single Lithium Primary State-of-Health and End-of-Service Monitor, PW0014A; Manufacturer: Texas Instruments; SymbolCreator: Altium; CompType: IC; U/M: EA

## Sheet TIDA-01546 Proj_SysLoad.SchDoc
size 431 x 279 mm; Date: Not shown in title block; ApprovedBy: Not shown in title block; CheckedBy: Not shown in title block; Author: Not shown in title block; CompanyName: Not shown in title block; Engineer: Not shown in title block; Organization: Not shown in title block; Address1: Not shown in title block; Address2: Not shown in title block; Address3: Not shown in title block; Address4: Not shown in title block; DocumentNumber: 1; Revision: Use project parameter SCH_Rev; SheetNumber: 2; SheetTotal: 3; PageSetup: Record=PageOptions¦CenterHorizontal=True¦CenterVertical=True¦PrintScale=1.00¦XCorrection=1.00¦YCorrection=1.00¦PrintKind=0¦BorderSize=5000000¦LeftOffset=0¦BottomOffset=0¦Orientation=2¦PaperLength=1000¦PaperWidth=1000¦Scale=100¦PaperSource=15¦PrintQuality=-3¦MediaType=1¦DitherType=10¦PrintScaleMode=1¦PaperKind=Letter¦PaperIndex=1
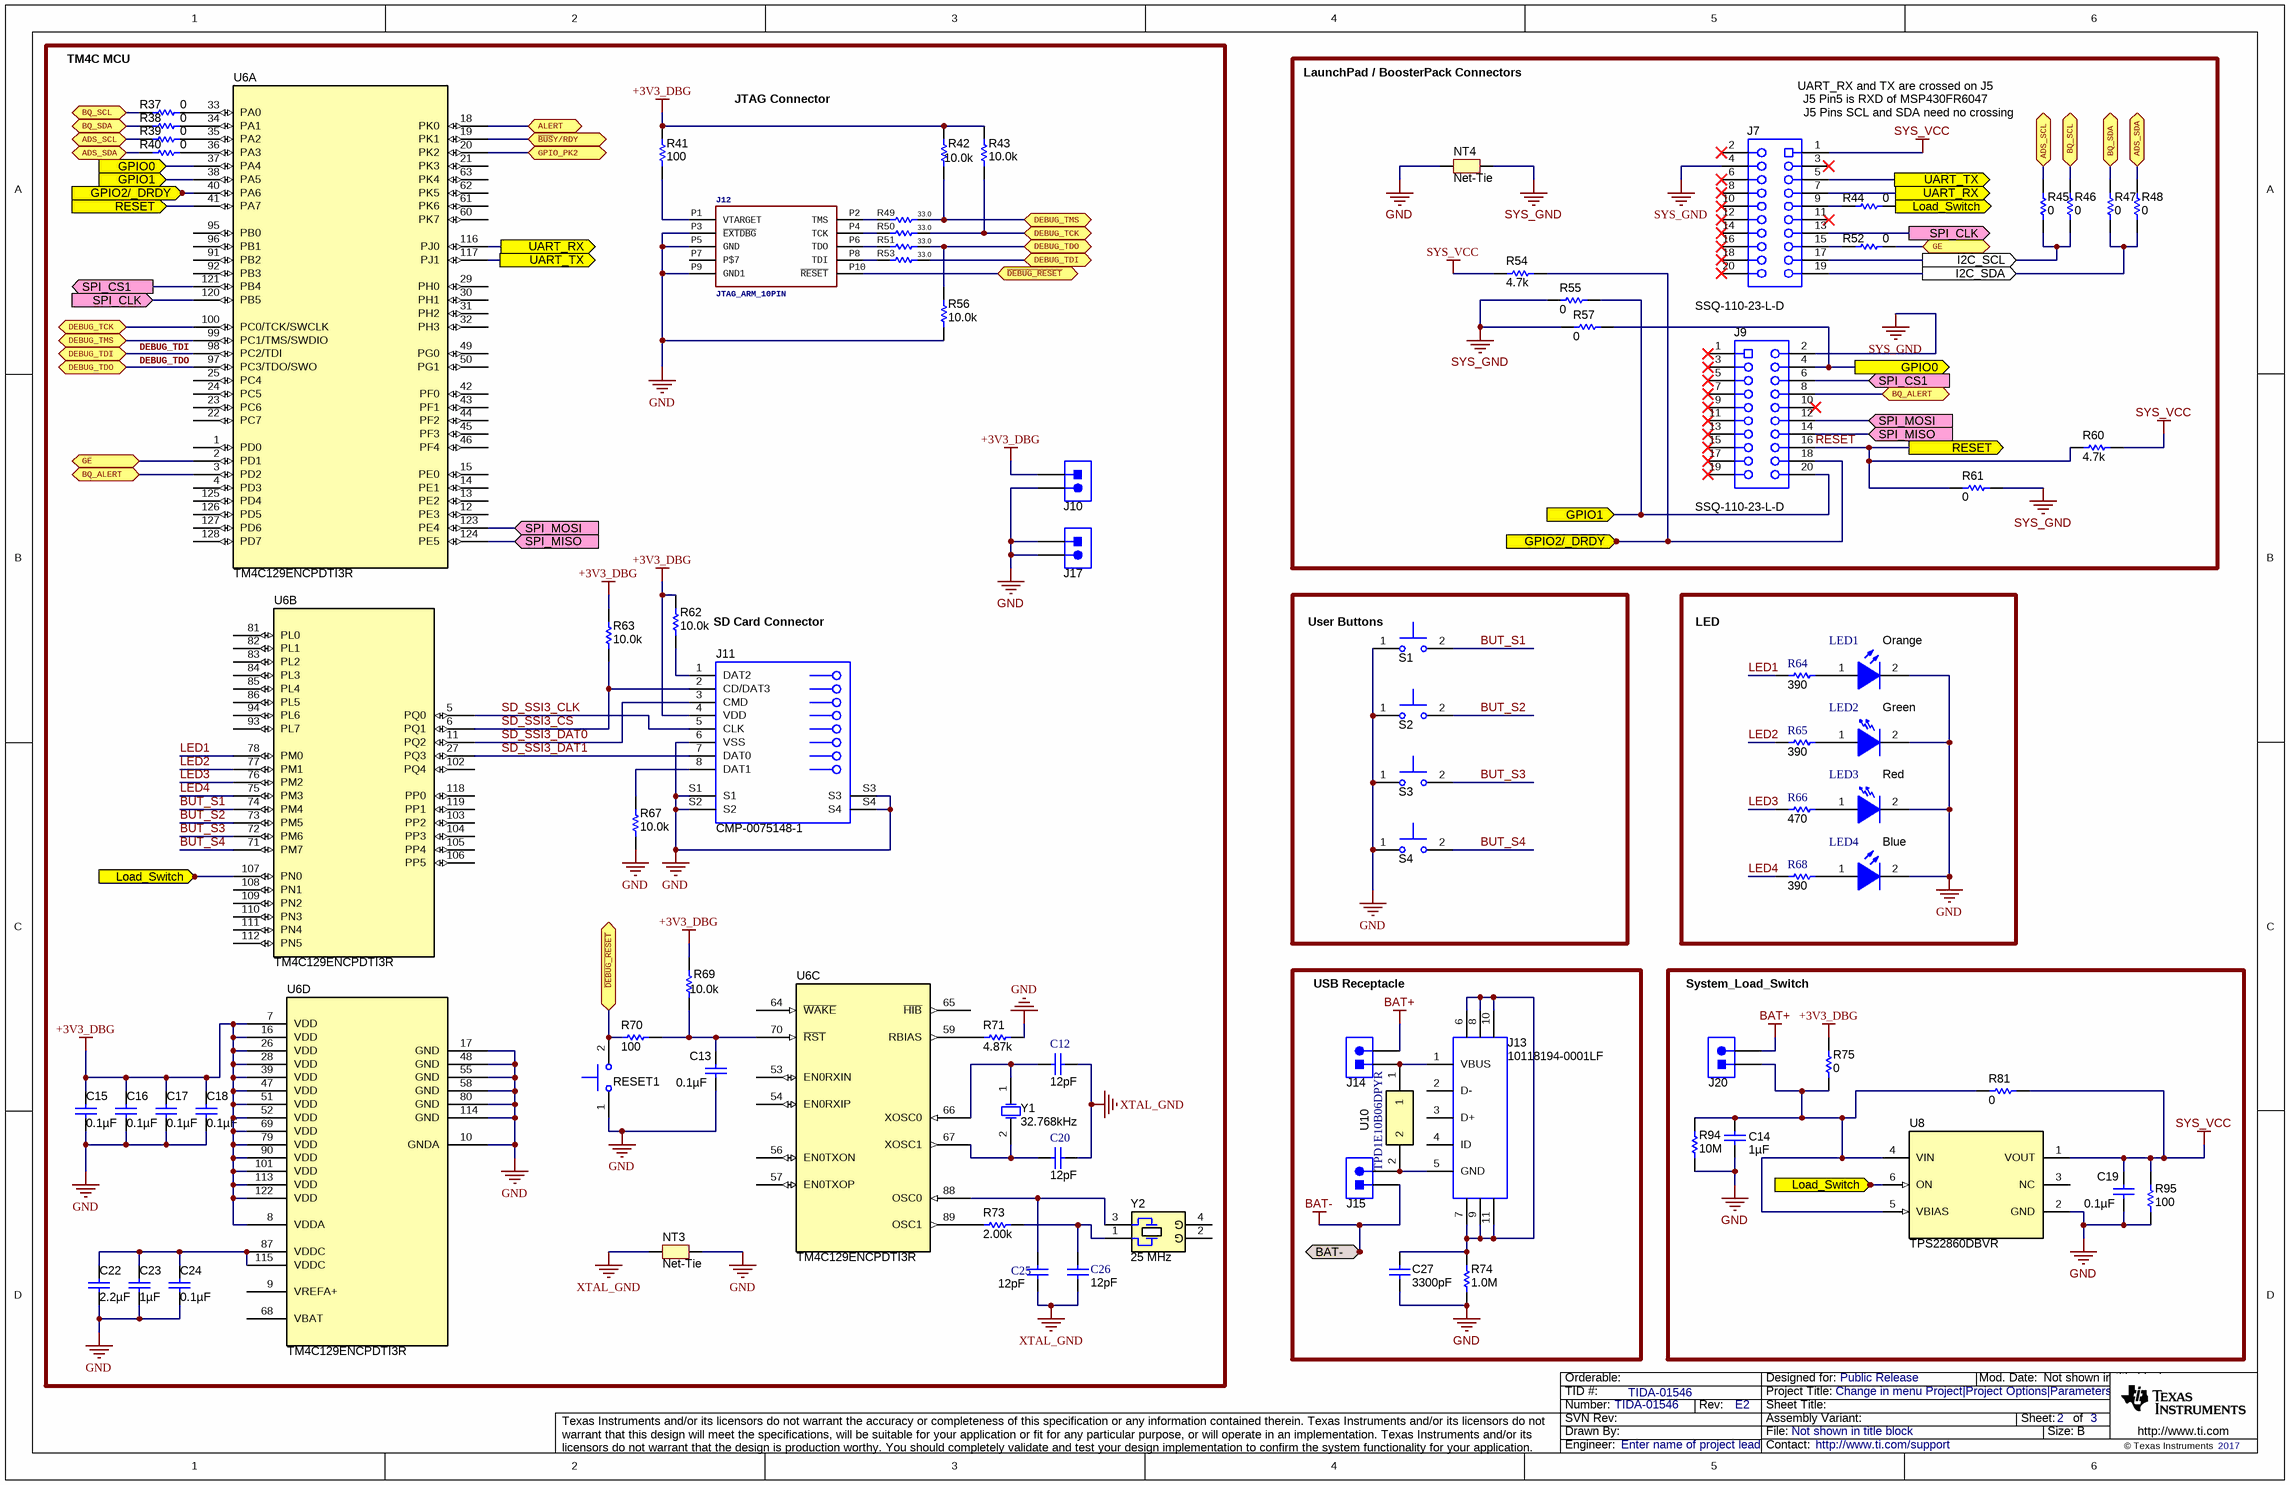
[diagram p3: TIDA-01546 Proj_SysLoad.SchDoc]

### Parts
C12  ValueDisplayed: 12pF  [0402S]  (hidden comment: GRM1555C1H120JA01D)
C13  ValueDisplayed: 0.1µF  [0402_065]  (hidden comment: 160R07X104KV4T)
C14  ValueDisplayed: 1µF  [0805_HV]  (hidden comment: 0805YD105KAT2A)
C15  ValueDisplayed: 0.1µF  [0402]  (hidden comment: GRM155R71C104KA88D)
C16  ValueDisplayed: 0.1µF  [0402]  (hidden comment: GRM155R71C104KA88D)
C17  ValueDisplayed: 0.1µF  [0402]  (hidden comment: GRM155R71C104KA88D)
C18  ValueDisplayed: 0.1µF  [0402]  (hidden comment: GRM155R71C104KA88D)
C19  ValueDisplayed: 0.1µF  [0603]  (hidden comment: C1608X7R1E104K080AA)
C20  ValueDisplayed: 12pF  [0402S]  (hidden comment: GRM1555C1H120JA01D)
C22  ValueDisplayed: 2.2µF  [0603]  (hidden comment: GRM188R61C225KE15D)
C23  ValueDisplayed: 1µF  [0805_HV]  (hidden comment: 0805YD105KAT2A)
C24  ValueDisplayed: 0.1µF  [0402]  (hidden comment: GRM155R71C104KA88D)
C25  ValueDisplayed: 12pF  [0402S]  (hidden comment: GRM1555C1H120JA01D)
C26  ValueDisplayed: 12pF  [0402S]  (hidden comment: GRM1555C1H120JA01D)
C27  ValueDisplayed: 3300pF  [0603]  (hidden comment: 06035C332KAT2A)
J7  SSW-110-23-F-D  [CONN_SSW-110-23-F-D]  (value not drawn)
J9  SSW-110-23-F-D  [CONN_SSW-110-23-F-D]  (value not drawn)
J10  PEC02SAAN  [CONN_PEC02SAAN]  (value not drawn)
J11  CMP-0075148-1  [3M_2908-05WB-MG]
J12  JTAG_ARM_10PIN  [CON_2X5_50MIL]
J13  10118194-0001LF  [FCI_10118194-0001LF]
J14  PEC02SAAN  [CONN_PEC02SAAN]  (value not drawn)
J15  PEC02SAAN  [CONN_PEC02SAAN]  (value not drawn)
J17  PEC02SAAN  [CONN_PEC02SAAN]  (value not drawn)
J20  PEC02SAAN  [CONN_PEC02SAAN]  (value not drawn)
LED1  value Orange  [LTST-C191_Orange]  (hidden comment: LTST-C191KFKT)
LED2  value Green  [LTST-C191_Green]  (hidden comment: LTST-C191TGKT)
LED3  value Red  [LED_LTST-C190_Red]  (hidden comment: LTST-C190CKT)
LED4  value Blue  [LTST-C193_Blue]  (hidden comment: LTST-C193TBKT-5A)
NT3  Net-Tie  [Net-Tie_50milWide_30milLong]  (net tie, no BOM)
NT4  Net-Tie  [Net-Tie_50milWide_30milLong]  (net tie, no BOM)
R37  ValueDisplayed: 0  [0402L]  (hidden comment: CRCW04020000Z0ED)
R38  ValueDisplayed: 0  [0402L]  (hidden comment: CRCW04020000Z0ED)
R39  ValueDisplayed: 0  [0402L]  (hidden comment: CRCW04020000Z0ED)
R40  ValueDisplayed: 0  [0402L]  (hidden comment: CRCW04020000Z0ED)
R41  ValueDisplayed: 100  [0603]  (hidden comment: CRCW0603100RFKEA)
R42  ValueDisplayed: 10.0k  [0603]  (hidden comment: CRCW060310K0FKEA)
R43  ValueDisplayed: 10.0k  [0603]  (hidden comment: CRCW060310K0FKEA)
R44  ValueDisplayed: 0  [0402L]  (hidden comment: CRCW04020000Z0ED)
R45  ValueDisplayed: 0  [0402L]  (hidden comment: CRCW04020000Z0ED)
R46  ValueDisplayed: 0  [0402L]  (hidden comment: CRCW04020000Z0ED)
R47  ValueDisplayed: 0  [0402L]  (hidden comment: CRCW04020000Z0ED)
R48  ValueDisplayed: 0  [0402L]  (hidden comment: CRCW04020000Z0ED)
R49  ValueDisplayed: 33.0  [0603]  (hidden comment: CRCW060333R0FKEA)
R50  ValueDisplayed: 33.0  [0603]  (hidden comment: CRCW060333R0FKEA)
R51  ValueDisplayed: 33.0  [0603]  (hidden comment: CRCW060333R0FKEA)
R52  ValueDisplayed: 0  [0402L]  (hidden comment: CRCW04020000Z0ED)
R53  ValueDisplayed: 33.0  [0603]  (hidden comment: CRCW060333R0FKEA)
R54  ValueDisplayed: 4.7k  [0402L]  (hidden comment: CRCW04024K70JNED)
R55  ValueDisplayed: 0  [0402L]  (hidden comment: CRCW04020000Z0ED)
R56  ValueDisplayed: 10.0k  [0603]  (hidden comment: CRCW060310K0FKEA)
R57  ValueDisplayed: 0  [0402L]  (hidden comment: CRCW04020000Z0ED)
R60  ValueDisplayed: 4.7k  [0402L]  (hidden comment: CRCW04024K70JNED)
R61  ValueDisplayed: 0  [0402L]  (hidden comment: CRCW04020000Z0ED)
R62  ValueDisplayed: 10.0k  [0603]  (hidden comment: CRCW060310K0FKEA)
R63  ValueDisplayed: 10.0k  [0603]  (hidden comment: CRCW060310K0FKEA)
R64  ValueDisplayed: 390  [0402S]  (hidden comment: CRCW0402390RJNED)
R65  ValueDisplayed: 390  [0402S]  (hidden comment: CRCW0402390RJNED)
R66  ValueDisplayed: 470  [0402S]  (hidden comment: CRCW0402470RJNED)
R67  ValueDisplayed: 10.0k  [0603]  (hidden comment: CRCW060310K0FKEA)
R68  ValueDisplayed: 390  [0402S]  (hidden comment: CRCW0402390RJNED)
R69  ValueDisplayed: 10.0k  [0603]  (hidden comment: CRCW060310K0FKEA)
R70  ValueDisplayed: 100  [0603]  (hidden comment: CRCW0603100RFKEA)
R71  ValueDisplayed: 4.87k  [0402]  (hidden comment: ERA-2AEB4871X)
R73  ValueDisplayed: 2.00k  [0402]  (hidden comment: ERJ-2RKF2001X)
R74  ValueDisplayed: 1.0M  [0603]  (hidden comment: CRCW06031M00JNEA)
R75  ValueDisplayed: 0  [0402L]  (hidden comment: CRCW04020000Z0ED)
R81  ValueDisplayed: 0  [0402L]  (hidden comment: CRCW04020000Z0ED)
R94  ValueDisplayed: 10M  [0402]  (hidden comment: CRCW040210M0JNED)
R95  ValueDisplayed: 100  [0603]  (hidden comment: CRCW0603100RFKEA)
RESET1  TL1015AF160QG  [SW_TL1015AF160QG]  (value not drawn)
S1  TL1015AF160QG  [SW_TL1015AF160QG]  (value not drawn)
S2  TL1015AF160QG  [SW_TL1015AF160QG]  (value not drawn)
S3  TL1015AF160QG  [SW_TL1015AF160QG]  (value not drawn)
S4  TL1015AF160QG  [SW_TL1015AF160QG]  (value not drawn)
U6  TM4C129ENCPDTI3R  [PDT0128A]  (parts A,B,C,D of 4)
U8  TPS22860DBVR  [DBV0006A_N]
U10  TPD1E10B06DPYR  [DPY0002A]
Y1  Frequency: 32.768kHz  [XTAL_ABS07]  (hidden comment: ABS07-32.768KHZ-9-T)
Y2  Frequency_Fixed: 25 MHz  [NDK_NX3225GA]  (hidden comment: NX3225GA-25.000M-STD-CRG-2)

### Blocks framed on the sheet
User Buttons: S1-S4
LED: LED1-LED4 R64-R66 R68
USB Receptacle: C27 J13-J15 R74 U10
System_Load_Switch: C14 C19 J20 R75 R81 R94 R95 U8

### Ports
ADS_SCL, ADS_SDA, ALERT, BAT- (bidir), BQ_ALERT, BQ_SCL, BQ_SDA, DEBUG_TCK, DEBUG_TDI, DEBUG_TDO, DEBUG_TMS, GE, GPIO0, GPIO1, GPIO2/_DRDY, GPIO_PK2, I2C_SCL, I2C_SDA, Load_Switch, RESET, SPI_CLK, SPI_CS1, SPI_MISO, SPI_MOSI, UART_RX, UART_TX, ~{BUS}Y/RDY, ~{DEBUG_RESET}

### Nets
+3V3_DBG: C15.2 C16.2 C17.2 C18.2 J10.1 J11.4(VDD) R41.1 R42.1 R43.1 R62.1 R63.1 R69.1 R75.1 U6.7(VDD) U6.8(VDDA) U6.16(VDD) U6.26(VDD) U6.28(VDD) U6.39(VDD) U6.47(VDD) U6.51(VDD) U6.52(VDD) U6.69(VDD) U6.79(VDD) U6.90(VDD) U6.101(VDD) U6.113(VDD) U6.122(VDD)
BAT+: J14.2 J20.2
BAT-: J15.1 ; port BAT-
GND: C13.1 C14.1 C15.1 C16.1 C17.1 C18.1 C19.1 C22.1 C23.1 C24.1 C27.1 J10.2 J11.6(VSS) J11.S1 J11.S2 J11.S3 J11.S4 J12.P3(~{EXTDBG}) J12.P5(GND) J12.P9(GND1) J17.1 J17.2 LED1.2(K) LED2.2(K) LED3.2(K) LED4.2(K) NT3.2 NT4.1 R56.2 R67.2 R71.2 R74.2 R94.1 R95.1 RESET1.1 S1.1 S2.1 S3.1 S4.1 U6.10(GNDA) U6.17(GND) U6.48(GND) U6.55(GND) U6.58(GND) U6.80(GND) U6.114(GND) U8.2(GND)
SYS_GND: J7.4 J9.2 NT4.2 R55.1 R57.1 R61.2
SYS_VCC: C19.2 J7.1 R54.1 R60.2 R81.2 R95.2 U8.1(VOUT)
XTAL_GND: C12.2 C20.1 C25.2 C26.2 NT3.1
ADS_SCL: R39.1 R45.1 ; port ADS_SCL
ADS_SDA: R40.2 R48.1 ; port ADS_SDA
ALERT: U6.18(PK0) ; port ALERT
~{BUS}Y/RDY: U6.19(PK1) ; port ~{BUS}Y/RDY
BQ_ALERT: J9.8 U6.3(PD2) ; port BQ_ALERT
BQ_SCL: R37.1 R46.1 ; port BQ_SCL
BQ_SDA: R38.2 R47.1 ; port BQ_SDA
BUT_S1: S1.2 U6.74(PM4)
BUT_S2: S2.2 U6.73(PM5)
BUT_S3: S3.2 U6.72(PM6)
BUT_S4: S4.2 U6.71(PM7)
~{DEBUG_RESET}: J12.P10(~{RESET}) R70.2 RESET1.2 ; port ~{DEBUG_RESET}
DEBUG_TCK: R43.2 R50.2 U6.100(PC0/TCK/SWCLK) ; port DEBUG_TCK
DEBUG_TDI: R53.2 U6.98(PC2/TDI) ; port DEBUG_TDI
DEBUG_TDO: R51.2 R56.1 U6.97(PC3/TDO/SWO) ; port DEBUG_TDO
DEBUG_TMS: R42.2 R49.2 U6.99(PC1/TMS/SWDIO) ; port DEBUG_TMS
GE: R52.1 U6.2(PD1) ; port GE
GPIO0: J9.4 R57.2 U6.37(PA4) ; port GPIO0
GPIO1: J9.20 R55.2 U6.38(PA5) ; port GPIO1
GPIO2/_DRDY: J9.18 R54.2 U6.40(PA6) ; port GPIO2/_DRDY
GPIO_PK2: U6.20(PK2) ; port GPIO_PK2
I2C_SCL: J7.17 R45.2 R46.2 ; port I2C_SCL
I2C_SDA: J7.19 R47.2 R48.2 ; port I2C_SDA
LED1: R64.1 U6.78(PM0)
LED2: R65.1 U6.77(PM1)
LED3: R66.1 U6.76(PM2)
LED4: R68.1 U6.75(PM3)
Load_Switch: R44.1 U6.107(PN0) U8.6(ON) ; port Load_Switch
RESET: J9.16 R60.1 R61.1 U6.41(PA7) ; port RESET
SD_SSI3_CLK: J11.5(CLK) U6.5(PQ0)
SD_SSI3_CS: J11.2(CD/DAT3) R63.2 U6.6(PQ1)
SD_SSI3_DAT0: J11.3(CMD) U6.11(PQ2)
SD_SSI3_DAT1: J11.7(DAT0) U6.27(PQ3)
SPI_CLK: J7.13 U6.120(PB5) ; port SPI_CLK
SPI_CS1: J9.6 U6.121(PB4) ; port SPI_CS1
SPI_MISO: J9.14 U6.124(PE5) ; port SPI_MISO
SPI_MOSI: J9.12 U6.123(PE4) ; port SPI_MOSI
UART_RX: J7.7 U6.116(PJ0) ; port UART_RX
UART_TX: J7.5 U6.117(PJ1) ; port UART_TX
NetC12_1: C12.1 U6.66(XOSC0) Y1.1(OSC1)
NetC13_2: C13.2 R69.2 R70.1 U6.70(~{RST})
NetC14_2: C14.2 J20.1 R75.2 R81.1 R94.2 U8.4(VIN) U8.5(VBIAS)
NetC20_2: C20.2 U6.67(XOSC1) Y1.2(OSC2)
NetC22_2: C22.2 C23.2 C24.2 U6.87(VDDC) U6.115(VDDC)
NetC25_1: C25.1 U6.88(OSC0) Y2.3
NetC26_1: C26.1 R73.2 Y2.1
NetC27_2: C27.2 J13.6 J13.7 J13.8 J13.9 J13.10 J13.11 R74.1
NetJ7_9: J7.9 R44.2
NetJ7_15: J7.15 R52.2
NetJ11_1: J11.1(DAT2) R62.2
NetJ11_8: J11.8(DAT1) R67.1
NetJ12_P1: J12.P1(VTARGET) R41.2
NetJ12_P2: J12.P2(TMS) R49.1
NetJ12_P4: J12.P4(TCK) R50.1
NetJ12_P6: J12.P6(TDO) R51.1
NetJ12_P8: J12.P8(TDI) R53.1
NetJ13_1: J13.1(VBUS) J14.1 U10.1
NetJ13_5: J13.5(GND) J15.2 U10.2
NetLED1_1: LED1.1(A) R64.2
NetLED2_1: LED2.1(A) R65.2
NetLED3_1: LED3.1(A) R66.2
NetLED4_1: LED4.1(A) R68.2
NetR37_2: R37.2 U6.33(PA0)
NetR38_1: R38.1 U6.34(PA1)
NetR39_2: R39.2 U6.35(PA2)
NetR40_1: R40.1 U6.36(PA3)
NetR71_1: R71.1 U6.59(RBIAS)
NetR73_1: R73.1 U6.89(OSC1)

Not connected (* = marked no-connect by the designer): J7 2* 3* 6* 8* 10* 11* 12* 14* 16* 18* 20*; J9 1* 3* 5* 7* 9* 10* 11* 13* 15* 17* 19*; J12 P7(P$7); J13 2(D-) 3(D+) 4(ID); U6 1(PD0) 4(PD3) 9(VREFA+) 12(PE3) 13(PE2) 14(PE1) 15(PE0) 21(PK3) 22(PC7) 23(PC6) 24(PC5) 25(PC4) 29(PH0) 30(PH1) 31(PH2) 32(PH3) 42(PF0) 43(PF1) 44(PF2) 45(PF3) 46(PF4) 49(PG0) 50(PG1) 53(EN0RXIN) 54(EN0RXIP) 56(EN0TXON) 57(EN0TXOP) 60(PK7) 61(PK6) 62(PK5) 63(PK4) 64(~{WAKE}) 65(~{HIB}) 68(VBAT) 81(PL0) 82(PL1) 83(PL2) 84(PL3) 85(PL4) 86(PL5) 91(PB2) 92(PB3) 93(PL7) 94(PL6) 95(PB0) 96(PB1) 102(PQ4) 103(PP2) 104(PP3) 105(PP4) 106(PP5) 108(PN1) 109(PN2) 110(PN3) 111(PN4) 112(PN5) 118(PP0) 119(PP1) 125(PD4) 126(PD5) 127(PD6) 128(PD7); U8 3(NC); Y2 2(GND) 4(GND)

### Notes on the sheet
- TM4C MCU
- JTAG Connector
- LaunchPad / BoosterPack Connectors
- UART_RX and TX are crossed on J5
- (near J7) J5 Pin5 is RXD of MSP430FR6047
- (near J7) J5 Pins SCL and SDA need no crossing
- (near J7) SSQ-110-23-L-D
- (near J9) SSQ-110-23-L-D
- SD Card Connector

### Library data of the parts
C12 C20 C25 C26 = GRM1555C1H120JA01D: CAP, CERM, 12 pF, 50 V, +/- 5%, C0G/NP0, 0402; Manufacturer: MuRata; Value: 12pF; Polarized: N; CompType: Capacitor; U/M: EA; Cap_F: 0.000000000012; Tolerance_%: 5; Value1: Unknown; VDC_V: 50; Value2: 50V; TaMin_C: -55; TaMax_C: 125; Cap_Case: 0402; AEC Category: Q200
C13 = 160R07X104KV4T: as C9 on sheet TIDA-01546 Proj_SysMonitoring
C14 C23 = 0805YD105KAT2A: CAP, CERM, 1 µF, 16 V,+/- 10%, X5R, 0805; Manufacturer: AVX; Polarized: N; CompType: Capacitor; Value: 1uF; U/M: EA; Cap_F: 0.000001; Tolerance_%: 10; ESR_ohm: 0.012; Value1: 0.012 ohm; VDC_V: 16; Value2: 16V; TaMin_C: -55; TaMax_C: 85; Cap_Case: 0805; SizeArea_mm2: 2.5; SizeAreaWB_mm2: 6.75; SizeX_mm: 2; SizeY_mm: 1.25; SizeZ_mm: 1.45; AEC Category: Q200; Green_Lifecycle: Active; Green_REACh: Passed
C15-C18 C24 = GRM155R71C104KA88D: CAP, CERM, 0.1 µF, 16 V,+/- 10%, X7R, 0402; Manufacturer: MuRata; Polarized: N; CompType: Capacitor; Value: 0.1uF; U/M: EA; Cap_F: 0.0000001; Tolerance_%: 10; VDC_V: 16; Value2: 16V; TaMin_C: -55; TaMax_C: 125; SizeArea_mm2: 0.5; SizeAreaWB_mm2: 3; SizeX_mm: 1; SizeZ_mm: 0.6; AEC Category: Q200; Green_Lifecycle: Active; Green_REACh: Passed
C19 = C1608X7R1E104K080AA: CAP, CERM, 0.1 µF, 25 V,+/- 10%, X7R, 0603; Manufacturer: TDK; Polarized: N; CompType: Capacitor; Value: 0.1uF; U/M: EA; Cap_F: 0.0000001; Tolerance_%: 10; VDC_V: 25; Value2: 25V; TaMin_C: -55; TaMax_C: 125; SizeArea_mm2: 1.28; SizeAreaWB_mm2: 4.68; SizeX_mm: 1.6; SizeY_mm: 0.8; SizeZ_mm: 1; AEC Category: Q200; Green_Lifecycle: NRND; Green_REACh: Passed
C22 = GRM188R61C225KE15D: CAP, CERM, 2.2 µF, 16 V,+/- 10%, X5R, 0603; Manufacturer: MuRata; Polarized: N; CompType: Capacitor; Value: 2.2uF; U/M: EA; Cap_F: 0.0000022; Tolerance_%: 10; VDC_V: 16; Value2: 16V; TaMin_C: -55; TaMax_C: 85; SizeArea_mm2: 1.28; SizeAreaWB_mm2: 4.68; SizeX_mm: 1.6; SizeY_mm: 0.8; SizeZ_mm: 1; AEC Category: Q200; Green_Lifecycle: Active; Green_REACh: Passed
C27 = 06035C332KAT2A: CAP, CERM, 3300 pF, 50 V,+/- 10%, X7R, 0603; Manufacturer: AVX; Polarized: N; CompType: Capacitor; Value: 3300pF; U/M: EA; Cap_F: 0.0000000033; Tolerance_%: 10; VDC_V: 50; Value2: 50V; TaMin_C: -55; TaMax_C: 125; SizeArea_mm2: 1.28; SizeAreaWB_mm2: 4.68; SizeX_mm: 1.6; SizeY_mm: 0.8; SizeZ_mm: 1; AEC Category: Q200; Green_Lifecycle: Active; Green_REACh: Passed
J7 J9 = SSW-110-23-F-D: Connector, Receptacle, 100mil, 10x2, Gold plated, TH; Manufacturer: Samtec; SymbolCreator: a0412235; U/M: EA
J10 J14 J15 J17 J20 = PEC02SAAN: as J4 on sheet TIDA-01546 Proj_SysMonitoring
J11 = CMP-0075148-1: Connector, Micro SD, R/A, SMD; PartNumber: 2908-05WB-MG; Manufacturer: 3M; Pitch_mm: 1.1; Gender: Female; Row_Count: 1; ContactFinish: Gold; CNHeader: False
J13 = 10118194-0001LF: Receptacle, USB 2.0, Micro-USB Type B, R/A, SMT; Manufacturer: FCI; SymbolCreator: a0411947; Pitch_mm: 0.65; Gender: Female; Row_Count: 1; ContactFinish: Gold; Current_A: 1.8; Voltage_V: 100; Cert_UL: Y
LED1 = LTST-C191KFKT: LED, Orange, SMD; Manufacturer: Lite-On; Type: AlInGaP; Vf_V: 2; Value2: 2V; Io_A: 0.02; Vr_V: 5; Ir_A: 1e-005; Tjmax_C: 85; Power_TotalModule: 0.075; Value1: 0.075W; Angle: 130; U/M: EA; Green_Lifecycle: Not Set; Green_REACh: Incomplete
LED2 = LTST-C191TGKT: LED, Green, SMD; Manufacturer: Lite-On; Type: InGaN; Vf_V: 3.2; Value2: 3.2V; Io_A: 0.02; Value1: W; U/M: EA
LED3 = LTST-C190CKT: LED, Red, SMD; Manufacturer: Lite-On; Vf_V: 2; Value2: 2V; Io_A: 0.02; Tjmax_C: 85; Power_TotalModule: 0.0625; Value1: 0.0625W; U/M: EA
LED4 = LTST-C193TBKT-5A: LED, Blue, SMD; Manufacturer: Lite-On; Type: InGaN; Vf_V: 2.8; Value2: 2.8V; Io_A: 0.005; Ir_A: 1e-005; Tjmax_C: 80; Power_TotalModule: 0.076; Value1: 0.076W; LuminousIntensity_IV: 15; Angle: 130; U/M: EA
NT3 NT4 = Net-Tie: as NT2 on sheet TIDA-01546 Proj_SysMonitoring
R37-R40 R44-R48 R52 R55 R57 R61 R75 R81 = CRCW04020000Z0ED: RES, 0, 5%, 0.063 W, 0402; Manufacturer: Vishay-Dale; CompType: Resistor; Value: 0; Value_Code: 0000; Tolerance_%: 5; Power_W: 0.063; Value2: 0.063W; VDC_V: 50; TempCo: 200 ppm/C; EIA_Code: E24; U/M: EA; AEC Category: Q200; SizeArea_mm2: 0.5; SizeX_mm: 1; SizeZ_mm: 0.6; Green_Lifecycle: Active; Green_REACh: Passed
R41 R70 R95 = CRCW0603100RFKEA: RES, 100, 1%, 0.1 W, 0603; Manufacturer: Vishay-Dale; CompType: Resistor; Value: 100; Value_Code: 100R; Tolerance_%: 1; Power_W: 0.1; Value2: 0.1W; VDC_V: 75; TempCo: 100 ppm/C; SizeArea_mm2: 1.28; SizeX_mm: 1.6; SizeY_mm: 0.8; EIA_Code: E96; U/M: EA; AEC Category: Q200; Green_Lifecycle: Active; Green_REACh: Passed
R42 R43 R56 R69 = CRCW060310K0FKEA: RES, 10.0 k, 1%, 0.1 W, 0603; Manufacturer: Vishay-Dale; CompType: Resistor; Value: 10.0k; Res_ohm: 10000; Value_Code: 10k0; Tolerance_%: 1; Power_W: 0.1; Value2: 0.1W; VDC_V: 75; TempCo: 100 ppm/C; SizeArea_mm2: 1.28; SizeX_mm: 1.6; SizeY_mm: 0.8; EIA_Code: E96; U/M: EA; AEC Category: Q200; Green_Lifecycle: Active; Green_REACh: Passed
R49-R51 R53 = CRCW060333R0FKEA: RES, 33.0, 1%, 0.1 W, 0603; Manufacturer: Vishay-Dale; CompType: Resistor; Value: 33.0; Res_ohm: 33; Value_Code: 33R0; Tolerance_%: 1; Power_W: 0.1; Value2: 0.1W; VDC_V: 75; TempCo: 100 ppm/C; SizeArea_mm2: 1.28; SizeX_mm: 1.6; SizeY_mm: 0.8; U/M: EA; AEC Category: Q200; Green_Lifecycle: Active; Green_REACh: Passed
R54 R60 = CRCW04024K70JNED: RES, 4.7 k, 5%, 0.063 W, 0402; Manufacturer: Vishay-Dale; CompType: Resistor; Value: 4.7k; Res_ohm: 4700; Value_Code: 4k70; Tolerance_%: 5; Power_W: 0.063; Value2: 0.063W; VDC_V: 50; TempCo: 200 ppm/C; EIA_Code: E24; U/M: EA; AEC Category: Q200; SizeArea_mm2: 0.5; SizeX_mm: 1; SizeZ_mm: 0.6; Green_Lifecycle: Active; Green_REACh: Passed
R62 R63 R67 = CRCW060310K0FKEA: as R3 on sheet TIDA-01546 Proj_BatMonitoring
R64 R65 R68 = CRCW0402390RJNED: RES, 390, 5%, 0.063 W, 0402; Manufacturer: Vishay-Dale; Value: 390; CompType: Resistor; Value_Code: 390R; Tolerance_%: 5; Power_W: 0.063; Value2: 0.063W; VDC_V: 50; TempCo: 200 ppm/C; EIA_Code: E24; U/M: EA; AEC Category: Q200
R66 = CRCW0402470RJNED: RES, 470, 5%, 0.063 W, 0402; Manufacturer: Vishay-Dale; Value: 470; CompType: Resistor; Value_Code: 470R; Tolerance_%: 5; Power_W: 0.063; Value2: 0.063W; VDC_V: 50; TempCo: 200 ppm/C; EIA_Code: E24; U/M: EA; AEC Category: Q200
R71 = ERA-2AEB4871X: RES, 4.87 k, 0.1%, 0.062 W, AEC-Q200 Grade 0, 0402; Manufacturer: Panasonic; CompType: Resistor; Value: 4.87k; Res_ohm: 4870; Value_Code: 4k87; Tolerance_%: 0.1; Power_W: 0.062; Value2: 0.062W; VDC_V: 25; TempCo: 25 ppm/C; SizeArea_mm2: 0.5; SizeX_mm: 1; SizeZ_mm: 0.6; EIA_Code: E192; U/M: EA; AEC Category: Q200; AEC Qualified: Y; AEC Grade: 0
R73 = ERJ-2RKF2001X: RES, 2.00 k, 1%, 0.1 W, AEC-Q200 Grade 0, 0402; Manufacturer: Panasonic; CompType: Resistor; Value: 2.00k; Res_ohm: 2000; Value_Code: 2k00; Tolerance_%: 1; Power_W: 0.1; Value2: 0.1W; VDC_V: 50; TempCo: 100 ppm/C; SizeArea_mm2: 0.5; SizeZ_mm: 0.6; EIA_Code: E96; U/M: EA; AEC Category: Q200; AEC Qualified: Y; AEC Grade: 0; Green_Lifecycle: Active; Green_REACh: Passed
R74 = CRCW06031M00JNEA: RES, 1.0 M, 5%, 0.1 W, 0603; Manufacturer: Vishay-Dale; CompType: Resistor; Value: 1.0Meg; Res_ohm: 1000000; Value_Code: 1M00; Tolerance_%: 5; Power_W: 0.1; Value2: 0.1W; VDC_V: 75; TempCo: 200 ppm/C; SizeArea_mm2: 1.28; SizeX_mm: 1.6; SizeY_mm: 0.8; SizeZ_mm: 1; EIA_Code: E24; U/M: EA; AEC Category: Q200; Green_Lifecycle: Active; Green_REACh: Passed
R94 = CRCW040210M0JNED: RES, 10 M, 5%, 0.063 W, 0402; Manufacturer: Vishay-Dale; CompType: Resistor; Value: 10Meg; Res_ohm: 10000000; Value_Code: 10M0; Tolerance_%: 5; Power_W: 0.063; Value2: 0.063W; VDC_V: 50; TempCo: 200 ppm/C; SizeArea_mm2: 0.5; SizeX_mm: 1; SizeZ_mm: 0.6; EIA_Code: E24; U/M: EA; AEC Category: Q200; Green_Lifecycle: Active; Green_REACh: Passed
RESET1 S1-S4 = TL1015AF160QG: Switch, Tactile, SPST-NO, 0.05A, 12V, SMT; Manufacturer: E-Switch; SymbolCreator: a0412235; VDC_V: 12; SwitchFunction: Off-Mom; PositionCount: 1; CurrentRating_mA: 50
U6 = TM4C129ENCPDTI3R: IoT enabled High performance 32-bit ARM(R) Cortex(R)-M4F based MCU, PDT0128A (TQFP-128); Manufacturer: Texas Instruments; SymbolCreator: a0411947; SizeArea_mm2: 256; SizeAreaWB_mm2: 324; SizeX_mm: 16; SizeZ_mm: 1.2; CompType: IC; U/M: EA
U8 = TPS22860DBVR: TPS22860 Ultra-low leakage load switch, DBV0006A (SOT-23-6); Manufacturer: Texas Instruments; SymbolCreator: Altium; SizeArea_mm2: 8.12; SizeAreaWB_mm2: 14.82; SizeX_mm: 2.8; SizeY_mm: 2.9; SizeZ_mm: 1.45; CompType: IC; U/M: EA; Green_Lifecycle: Active; Green_REACh: Passed
U10 = TPD1E10B06DPYR: as U1 on sheet TIDA-01546 Proj_BatMonitoring
Y1 = ABS07-32.768KHZ-9-T: CRYSTAL, 32.768KHZ, 9PF, SMD; Manufacturer: Abracon Corporation; SymbolCreator: a0412235; U/M: EA; TaMin_C: -40; TaMax_C: 85; Frequency Stability: ±20ppm
Y2 = NX3225GA-25.000M-STD-CRG-2: Crystal, 25 MHz, 8pF, SMD; Manufacturer: NDK; SymbolCreator: a0412235; U/M: EA; TaMin_C: -40; TaMax_C: 85; Frequency Stability: ±30ppm

## Sheet TIDA-01546 Proj_EVM_Hardware.SchDoc
size 431 x 279 mm; Date: Not shown in title block; ApprovedBy: Not shown in title block; CheckedBy: Not shown in title block; Author: Not shown in title block; CompanyName: Not shown in title block; Engineer: Not shown in title block; Organization: Not shown in title block; Address1: Not shown in title block; Address2: Not shown in title block; Address3: Not shown in title block; Address4: Not shown in title block; DocumentNumber: 1; Revision: Use project parameter SCH_Rev; SheetNumber: 3; SheetTotal: 3; PageSetup: Record=PageOptions¦CenterHorizontal=True¦CenterVertical=True¦PrintScale=1.00¦XCorrection=1.00¦YCorrection=1.00¦PrintKind=0¦BorderSize=5000000¦LeftOffset=0¦BottomOffset=0¦Orientation=2¦PaperLength=1000¦PaperWidth=1000¦Scale=100¦PaperSource=15¦PrintQuality=600¦MediaType=1¦DitherType=10¦PaperKind=Letter¦PrintScaleMode=1
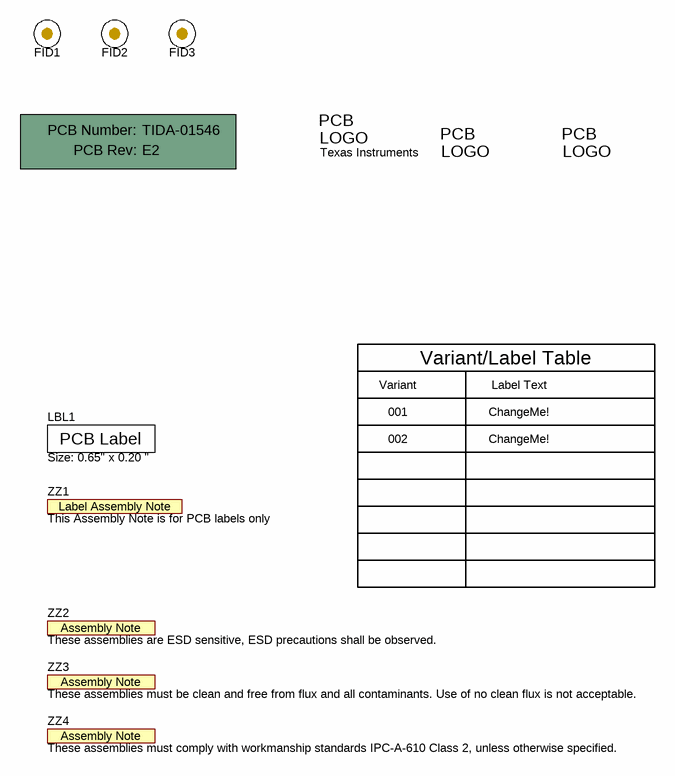
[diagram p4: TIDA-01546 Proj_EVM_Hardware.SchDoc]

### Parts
!PCB1  Printed Circuit Board  (value not drawn)  (mechanical)
FID1  Fiducial  [Fiducial10-20]  (value not drawn)
FID2  Fiducial  [Fiducial10-20]  (value not drawn)
FID3  Fiducial  [Fiducial10-20]  (value not drawn)
LBL1  Size: 0.65" x 0.20 "  [Label_650x200]
Logo1  Texas Instruments  [TI_Symbol_Overlay_Small]  (no BOM)
Logo2  Pb-Free Symbol  [Pb-Free_Overlay_Small]  (value not drawn)  (no BOM)
Logo3  FCC disclaimer  [FCC_disclaimer]  (value not drawn)  (no BOM)
ZZ1  This Assembly Note is for PCB labels only  [AssemblyNoteLabel]  (no BOM)
ZZ2  These assemblies are ESD sensitive, ESD precautions shall be observed.  [AssemblyNote]  (no BOM)
ZZ3  These assemblies must be clean and free from flux and all contaminants. Use of no clean flux is not acceptable.  [AssemblyNote]  (no BOM)
ZZ4  These assemblies must comply with workmanship standards IPC-A-610 Class 2, unless otherwise specified.  [AssemblyNote]  (no BOM)

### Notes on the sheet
- Variant
- Variant/Label Table
- Label Text
- 001
- 002
- ChangeMe!

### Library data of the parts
!PCB1 = PCB: Manufacturer: Any; PartNumber: TIDA-01546; SymbolCreator: a0412235
FID1-FID3 = Fiducial: Fiducial mark.  There is nothing to buy or mount.; SymbolCreator: codlsc
LBL1 = THT-14-423-10: Thermal Transfer Printable Labels, 0.650" W x 0.200" H - 10,000 per roll; Manufacturer: Brady; SymbolCreator: a0412235; CompType: Label; Green_Lifecycle: Not Set; Green_REACh: Incomplete
Logo1 = TI_Logo: Texas Instrument Corporate Signature; SymbolCreator: codlsc
Logo2 = Pb-Free: SymbolCreator: a0412235
Logo3 = FCC_disclaimer: SymbolCreator: a0412235
ZZ1 = AssemblyNoteLabel: SymbolCreator: a0412235
ZZ2-ZZ4 = AssemblyNote: SymbolCreator: codlsc

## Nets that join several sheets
+3V3_DBG: TIDA-01546 Proj_SysMonitoring (J5.1 R26.1 R29.1 R30.1), TIDA-01546 Proj_BatMonitoring (J16.1), TIDA-01546 Proj_SysLoad (28 pins)
BAT+: TIDA-01546 Proj_SysMonitoring (J4.1), TIDA-01546 Proj_BatMonitoring (J1.2 J1.4 J1.6 J3.1), TIDA-01546 Proj_SysLoad (J14.2 J20.2)
BAT-: TIDA-01546 Proj_SysMonitoring (5 pins), TIDA-01546 Proj_BatMonitoring (J3.2 R17.1 R19.1 TP8.1), TIDA-01546 Proj_SysLoad (J15.1)
GND: TIDA-01546 Proj_SysMonitoring (9 pins), TIDA-01546 Proj_BatMonitoring (17 pins), TIDA-01546 Proj_SysLoad (47 pins)
SYS_VCC: TIDA-01546 Proj_SysMonitoring (J6.1), TIDA-01546 Proj_SysLoad (7 pins)
ADS_SCL: TIDA-01546 Proj_SysMonitoring (R29.2 TP11.1 U4.8), TIDA-01546 Proj_SysLoad (R39.1 R45.1)
ADS_SDA: TIDA-01546 Proj_SysMonitoring (R30.2 TP12.1 U4.7), TIDA-01546 Proj_SysLoad (R40.2 R48.1)
ALERT: TIDA-01546 Proj_SysMonitoring (R26.2 TP10.1 U4.6), TIDA-01546 Proj_SysLoad (U6.18)
~{BUS}Y/RDY: TIDA-01546 Proj_SysMonitoring (U4.5), TIDA-01546 Proj_SysLoad (U6.19)
BQ_ALERT: TIDA-01546 Proj_BatMonitoring (R16.2), TIDA-01546 Proj_SysLoad (J9.8 U6.3)
BQ_SCL: TIDA-01546 Proj_BatMonitoring (J18.2 R7.2 TP5.1 U2.1), TIDA-01546 Proj_SysLoad (R37.1 R46.1)
BQ_SDA: TIDA-01546 Proj_BatMonitoring (J18.1 R6.2 TP4.1 U1.1), TIDA-01546 Proj_SysLoad (R38.2 R47.1)
GE: TIDA-01546 Proj_BatMonitoring (R22.2), TIDA-01546 Proj_SysLoad (R52.1 U6.2)
GPIO_PK2: TIDA-01546 Proj_SysMonitoring (Q4.1 R36.1), TIDA-01546 Proj_SysLoad (U6.20)

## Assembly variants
TIDA_01546_Inverting: not fitted FID1 FID2 FID3 R19 R28 R35 R45 R46 R47 R48 R55 R57 R61 R75 R81 R90 R94 R95
TIDA_01546_NonInverting: not fitted FID1 FID2 FID3 R19 R35 R45 R46 R47 R48 R55 R57 R61 R75 R81 R92 R93 R94 R95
